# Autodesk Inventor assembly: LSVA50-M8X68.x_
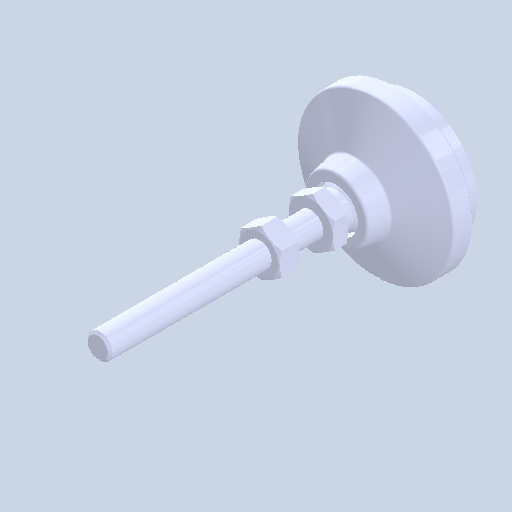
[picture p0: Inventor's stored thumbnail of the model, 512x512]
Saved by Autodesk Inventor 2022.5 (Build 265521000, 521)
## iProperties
Created: 2024-08
Part Number: LSVA50-M8X68.x_
Document SubType Name: Assembly
Designer: ImaoCorp
Author: ImaoCorp
Sending System: SOLIDWORKS 2022-2022290
MC: AMD64
MC_MODEL: Intel64 Family 6 Model 60 Stepping 3, GenuineIntel
OS: Windows_NT
FRU: Parasolid Version 33.1, build 260,  4-25-2022
FORMAT: text
GUISE: transmit
KEY: FILELSVA50-M8X68.x_t
DATE: Fri Aug 23 16:08:53 2024
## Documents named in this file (4)
- X:\14_SW2022-Inv2022\06_2024-10新製品(SME)\ELS_データ\l\lsva50-m8x68\LSVA50-M8X68.x_.iam
- X:\14_SW2022-Inv2022\06_2024-10新製品(SME)\ELS_データ\l\lsva50-m8x68\LSVA50-M8X68_01.ipt
- X:\14_SW2022-Inv2022\06_2024-10新製品(SME)\ELS_データ\l\lsva50-m8x68\LSVA50-M8X68_02.ipt
- X:\14_SW2022-Inv2022\06_2024-10新製品(SME)\ELS_データ\l\lsva50-m8x68\LSVA50-M8X68_03.ipt
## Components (3 placed, 3 different names)
1. LSVA50-M8X68_01
2. LSVA50-M8X68_02
3. LSVA50-M8X68_03
